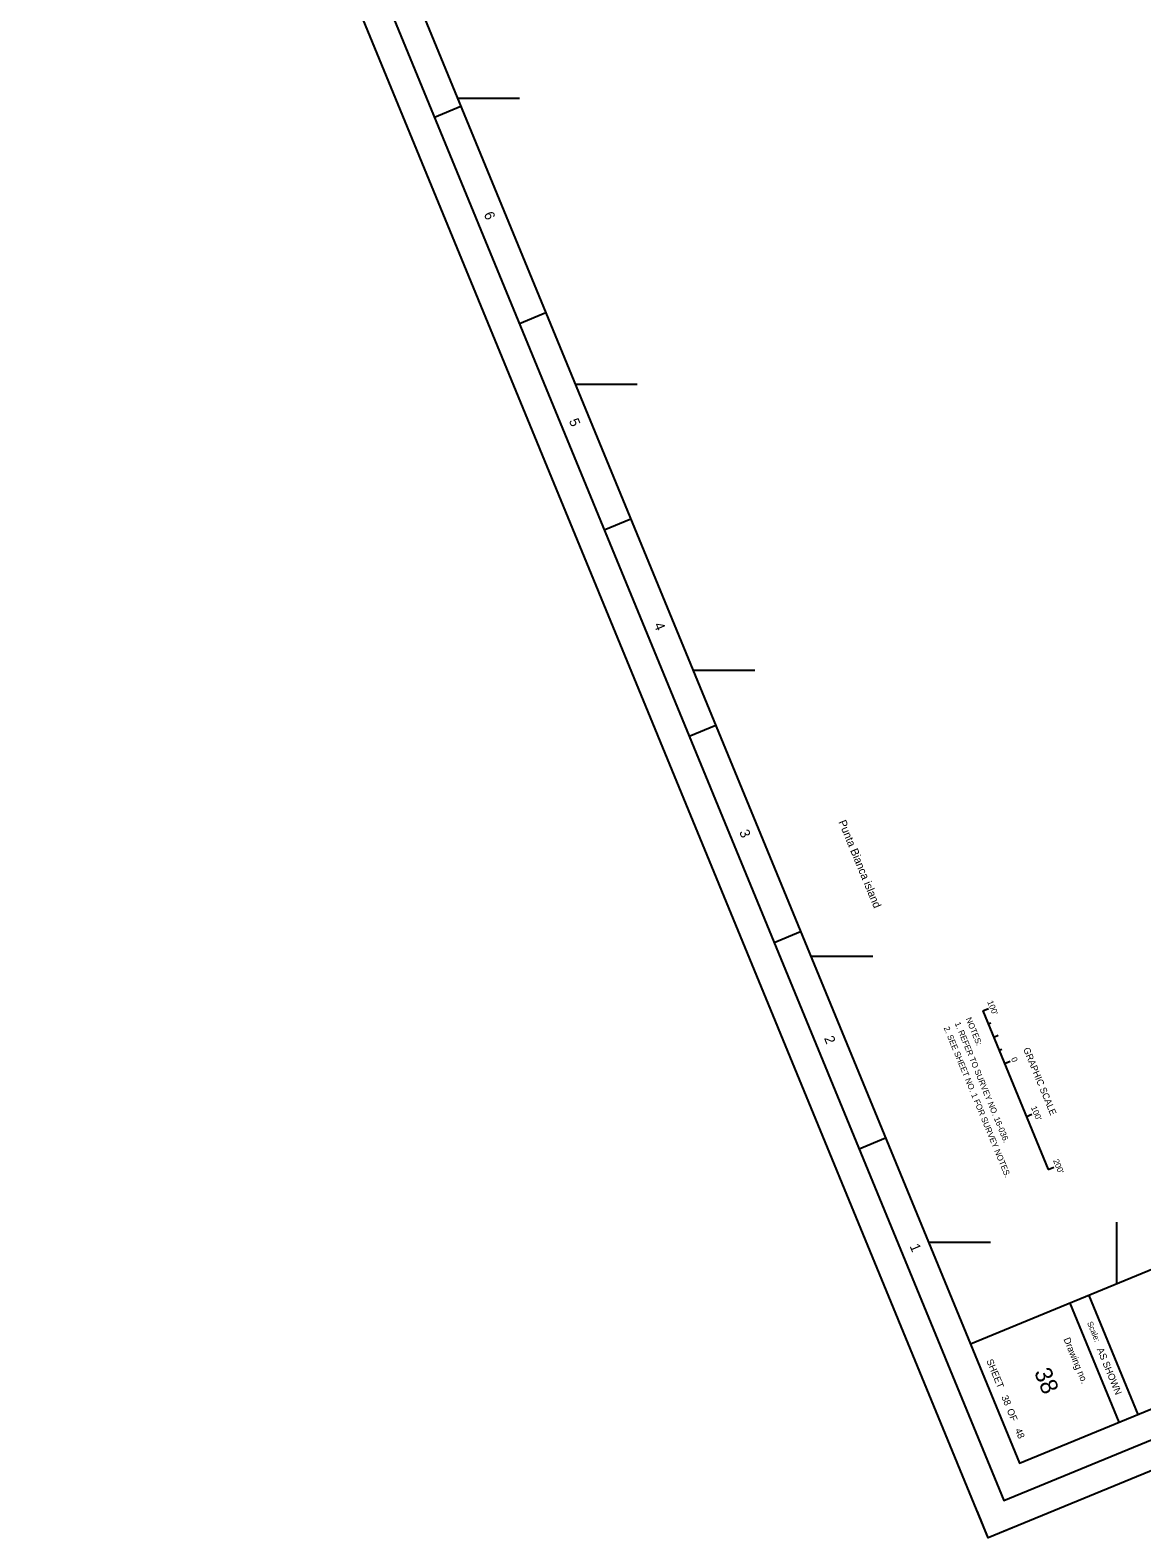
# Model space of a CAD drawing. Extents: x 579601 to 584420, y 852483 to 857846.
# Drawn here: x 579601 to 581544, y 852483 to 855119 of the extents above; entities that cross this region are included whole.
import ezdxf

# ---------------------------------------------------------------- set-up
doc = ezdxf.new("R2010")
doc.units = 0
for name, color, linetype in [('G-ANNO-NPLT', 7, 'Continuous'), ('G-ANNO-TEXT-DRWG', 7, 'Continuous'), ('G-ANNO-TEXT-TTLB', 7, 'Continuous'), ('G-ANNO-TTLB', 7, 'Continuous'), ('V-ANNO-NOTE', 7, 'Continuous'), ('V-SITE-IDEN', 7, 'Continuous'), ('V-TOPO-COOR-STAT', 7, 'Continuous')]:
    doc.layers.add(name, color=color, linetype=linetype)

msp = doc.modelspace()

# ---------------------------------------------------------------- linework, layer by layer
at = {"layer": 'G-ANNO-NPLT'}
msp.add_lwpolyline([(582745.7, 857846.1), (584419.8, 853777), (581275.5, 852483.4), (579601.4, 856552.5)], close=True, dxfattribs=at)
msp.add_lwpolyline([(581321.8, 852502.3), (581275.5, 852483.3), (581256.5, 852529.5)], dxfattribs=at)
at = {"layer": 'G-ANNO-TTLB'}
for p, q in [((580307.8, 854967), (580354, 854986)), ((580456.2, 854606.3), (580502.4, 854625.3)), ((580604.5, 854245.6), (580650.8, 854264.7)), ((584203.6, 854039.5), (581244.3, 852822)), ((580752.9, 853885), (580799.2, 853904)), ((580901.3, 853524.3), (580947.5, 853543.3)), ((581049.7, 853163.6), (581095.9, 853182.7)), ((581451.2, 852907.2), (581536.8, 852699.1)), ((581418.2, 852893.6), (581503.8, 852685.5))]:
    msp.add_line(p, q, dxfattribs=at)
for points in [[(579666.7, 856525.2), (581302.7, 852548.7), (584354.5, 853804.2), (582718.5, 857780.8)], [(584289.2, 853831.4), (582719.8, 857646.2), (579760.5, 856428.7), (581329.9, 852613.9)]]:
    msp.add_lwpolyline(points, close=True, dxfattribs=at)
at = {"layer": 'V-ANNO-NOTE'}
for p, q in [((581265.9, 853404.9), (581275.6, 853408.9)), ((581265.9, 853404.9), (581380, 853127.5)), ((581275.4, 853381.8), (581279.8, 853383.6)), ((581284.9, 853358.7), (581292.8, 853361.9)), ((581294.4, 853335.6), (581298.9, 853337.4)), ((581303.9, 853312.4), (581313.6, 853316.4)), ((581303.9, 853312.4), (581313.6, 853316.4)), ((581303.9, 853312.4), (581308.6, 853314.3)), ((581342, 853220), (581351.7, 853223.9)), ((581380, 853127.5), (581389.7, 853131.5))]:
    msp.add_line(p, q, dxfattribs=at)
at = {"layer": 'V-TOPO-COOR-STAT'}
for p, q in [((580348.2, 855000), (580456.4, 855000)), ((580554, 854500), (580662.1, 854500)), ((580759.7, 854000), (580867.8, 854000)), ((580965.4, 853500), (581073.5, 853500)), ((581500, 852927.2), (581500, 853035.4)), ((581171.1, 853000), (581279.2, 853000))]:
    msp.add_line(p, q, dxfattribs=at)

# ---------------------------------------------------------------- texts
at = {"layer": 'G-ANNO-TEXT-DRWG'}
for s, height, p in [('38', 30, (581355, 852773.1)), (' 38          48', 12, (581296.3, 852733.7))]:
    msp.add_text(s, height=height, rotation=292.363, dxfattribs=at).set_placement(p)
at = {"layer": 'G-ANNO-TEXT-TTLB'}
for s, height, p in [('Scale:', 10, (581447.9, 852859.1)), ('Drawing no.', 12, (581406.6, 852830.6)), ('AS SHOWN', 12, (581464.9, 852812.8)), ('SHEET         OF', 12, (581271.9, 852792.9))]:
    msp.add_text(s, height=height, rotation=292.363, dxfattribs=at).set_placement(p)
at = {"layer": 'G-ANNO-TTLB'}
for s, p in [('6', (580393.7, 854797.6)), ('5', (580542.4, 854436.2)), ('4', (580690.8, 854079.7)), ('3', (580839.9, 853717.3)), ('2', (580988.2, 853356.8)), ('1', (581137.8, 852993.3))]:
    msp.add_text(s, height=17.5, rotation=292.363, dxfattribs=at).set_placement(p)
at = {"layer": 'V-ANNO-NOTE'}
for s, height, p in [("100'", 10.42, (581273.4, 853420.2)), ('2. SEE SHEET NO. 1 FOR SURVEY NOTES.', 10.416, (581197.3, 853374.8)), ('1. REFER TO SURVEY NO. 16-036.', 10.416, (581216.6, 853382.7)), ('NOTES:', 10.42, (581235.8, 853390.7)), ('GRAPHIC SCALE', 11.666, (581336.2, 853337.8)), ('0', 10.4, (581314.9, 853321)), ("100'", 10.42, (581349.7, 853235.7)), ("200'", 10.42, (581388.4, 853142.9))]:
    msp.add_text(s, height=height, rotation=292.363, dxfattribs=at).set_placement(p)
at = {"layer": 'V-SITE-IDEN'}
msp.add_text('Punta Bianca island', height=13.92, rotation=292.363, dxfattribs=at).set_placement((581013.4, 853734.9))

doc.saveas('drawing.dxf')
